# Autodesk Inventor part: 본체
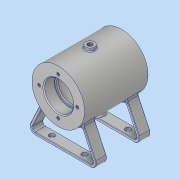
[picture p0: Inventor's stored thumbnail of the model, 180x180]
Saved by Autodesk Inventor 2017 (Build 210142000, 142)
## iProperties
Part Number: 본체
Material: 알루미늄 6061
Document SubType Name: Modeling
Designer: Administrator
Density: 2.7 g/cm^3
Appearance: 알루미늄 - 평지
Mass: 309.814 g
Surface Area: 357.327 cm^2
Volume: 114.746 cm^3
Author: Administrator
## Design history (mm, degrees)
sketch "스케치1"
  geometry: C1 r 29 at (0, 0); 1 further point
  constraints: 1 centre point, 1 coincident
  dimensions: "d0" = 58 diameter of C1
extrude "돌출1" new body sketch "스케치1" stored distance "d1" = 70; taper "d2" = 0 deg
sketch "스케치2"
  geometry: C1 r 16 at (0, 0); 1 further point
  constraints: 1 centre point, 1 coincident
  dimensions: "d3" = 32 diameter of C1
extrude "돌출2" cut sketch "스케치2" distance "d4" = 12; taper "d5" = 0 deg
sketch "스케치3"
  geometry: C1 r 14 at (0, 0); 1 further point
  constraints: 1 centre point, 1 coincident
  dimensions: "d6" = 28 diameter of C1
extrude "돌출3" cut sketch "스케치3" distance "d7" = 2; taper "d8" = 0 deg
sketch "스케치4"
  geometry: C1 r 21 at (0, 0); 1 further point
  constraints: 1 centre point, 1 coincident
  dimensions: "d9" = 42 diameter of C1
extrude "돌출4" cut sketch "스케치4" distance "d10" = 42; taper "d11" = 0 deg
sketch "스케치5" dims "d12" = 42
  geometry: 3 further points
  constraints: 2 vertical alignment, 1 coincident, 2 other
hole "구멍1" sketch "스케치5" at (0, 21) diameter "d13" = 3.242; stored, may be unused: countersink angle "d17" = 90 deg, drill point angle "d19" = 118 deg; dims "d14" = 8, "d15" = 4, "d16" = 2, "d18" = 10
node "작업 평면2"
sketch "스케치7"
  geometry: C1 r 5 at (0, 0); 1 further point
  constraints: 1 centre point, 1 coincident
  dimensions: "d28" = 10 diameter of C1
extrude "돌출6" join sketch "스케치7" stored distance "d29" = 42; taper "d30" = 0 deg
sketch "스케치8"
  geometry: 1 further point
hole "구멍2" sketch "스케치8" at (0, 0) diameter "d31" = 5.188; stored, may be unused: countersink angle "d35" = 90 deg, drill point angle "d37" = 118 deg; dims "d32" = 6, "d33" = 4, "d34" = 2, "d36" = 8
sketch "스케치9"
  geometry: C1 r 1.5 at (0, 0); 1 further point
  constraints: 1 centre point, 1 coincident
  dimensions: "d38" = 3 diameter of C1
extrude "돌출7" cut sketch "스케치9" distance "d39" = 16; taper "d40" = 0 deg
node "작업 평면3"
sketch "스케치10"
  geometry: L1 (-40, -55)-(40, -55); L2 (-35.291, -52)-(35.291, -52); L3 (-35.291, -52)-(-18.723, -16.469); L4 (-40, -55)-(-22.033, -16.469); L5 (-22.033, -16.469)-(-18.723, -16.469); L6 (35.291, -52)-(18.723, -16.469); L7 (18.723, -16.469)-(22.033, -16.469); L8 (22.033, -16.469)-(40, -55); C1 r 29 at (0, 0) reference; C2 r 1.621 at (21, 0) reference; C3 r 1.621 at (0, -21) reference; C4 r 1.621 at (-21, 0) reference; C5 r 1.621 at (0, 21) reference; C6 r 16 at (0, 0) reference; C7 r 29 at (0, 0) reference; 2 further points
  constraints: 16 end point, 3 horizontal, 3 parallel, 1 horizontal alignment, 1 midpoint, 1 vertical alignment
  dimensions: "d43" = 3 distance between parallel lines of L1 L2; "d44" = 55 distance from line of L1 point (0, 0); "d48" = 80 distance of L1.start L1.end; "d51" = 65 deg angle of L1 L8; "d52" = 65 deg angle of L1 L4; "d53" = 3 distance between parallel lines of L3 L4; "d54" = 3 distance between parallel lines of L8 L6; "d56" = 16.4693 distance from line of L5 C1.centre
extrude "돌출8" join sketch "스케치10" distance "d57" = 12; taper "d58" = 0 deg
sketch "스케치11"
  geometry: L1 (70.582, 0)-(70.582, 12) reference; L2 (0, 12)-(70.582, 12) reference; L3 (-3.31, 12)-(0, 12) reference; L4 (-3.31, 0)-(-3.31, 12) reference; L5 (0, 0)-(-3.31, 0) reference; L6 (70.582, 0)-(0, 0) reference; L7 (73.892, 0)-(70.582, 0) reference; L8 (73.892, 12)-(73.892, 0) reference; L9 (70.582, 12)-(73.892, 12) reference; L10 (0, 12)-(0, 0) reference; L11 (-4.709, 0)-(-4.709, 12) reference; C1 r 3 at (17.291, 6); C2 r 3 at (53.291, 6); 1 further point
  constraints: 2 centre point, 1 horizontal alignment
  dimensions: "d59" = 6 diameter of C1; "d60" = 6 diameter of C2; "d61" = 6 distance from line of C1.centre L2; "d62" = 36 distance of C2.centre C1.centre; "d63" = 22 distance from line of C1.centre L11
extrude "돌출9" cut sketch "스케치11" stored distance "d64" = 12; taper "d65" = 0 deg
node "작업 평면5"
  node "작업 평면4"
sketch "스케치12"
  geometry: C1 r 6 at (0, 0); 1 further point
  constraints: 1 centre point, 1 coincident
  dimensions: "d68" = 12 diameter of C1
extrude "돌출10" join sketch "스케치12" stored distance "d69" = 12; taper "d70" = 0 deg
sketch "스케치13"
  geometry: 1 further point
hole "구멍3" sketch "스케치13" at (0, 0) diameter "d71" = 5.188; stored, may be unused: countersink angle "d75" = 90 deg, drill point angle "d77" = 118 deg; dims "d72" = 25, "d73" = 4, "d74" = 2, "d76" = 29.5
fillet "모깎기1" dims "d78" = 6
fillet "모깎기3" dims "d80" = 1
chamfer "모따기1" distance "d82" = 1; stored, may be unused: second distance "d83" = 2, angle "d84" = 45 deg
fillet "모깎기5" dims "d85" = 3, "d86" = 0.3
node "작업 평면6"
sketch "스케치14"
  geometry: L1 (-29, -35)-(29, -35) reference; L2 (-29, -35)-(-29, 35) reference; 2 further points
  constraints: 1 other
  dimensions: "d87" = 35 distance from line of point (0, 0) L1; "d88" = 29 distance from line of point (0, 0) L2
feature "엠보싱1" sketch "스케치14" dims "d89" = 0.5, "d90" = 0
fillet "모깎기8" dims "d93" = 3
fillet "모깎기9" dims "d94" = 0.5
fillet "모깎기10" dims "d95" = 3
node "솔리드1"
pattern_circular "원형 패턴1" dims angle "d21" = 360 deg
mirror "미러1"
mirror "미러2"
node "절단 모서리 투영1"
node "절단 모서리 투영2"
other parameters: "d27" = 32, "d41" = -5, "d66" = 110 deg, "d67" = -32
